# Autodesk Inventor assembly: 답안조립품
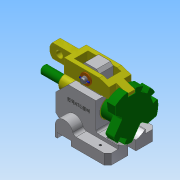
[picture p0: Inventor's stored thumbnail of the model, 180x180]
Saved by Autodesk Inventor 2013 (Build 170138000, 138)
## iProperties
Created: 2016-11
Part Number: 답안조립품
Document SubType Name: Assembly
Designer: Administrator
Author: Administrator
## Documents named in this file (8)
- C:\Users\Administrator\Desktop\461108V1013\답안조립품.iam
- C:\Users\Administrator\Desktop\461108V1013\본체.ipt
- C:\Users\Administrator\Desktop\461108V1013\부시.ipt
- C:\Users\Administrator\Desktop\461108V1013\분할대.ipt
- C:\Users\Administrator\Desktop\461108V1013\분할축.ipt
- C:\Users\Administrator\Desktop\461108V1013\와셔.ipt
- C:\Users\Administrator\Desktop\461108V1013\원통형핀.ipt
- C:\Users\Administrator\Desktop\461108V1013\클레비스핀.ipt
